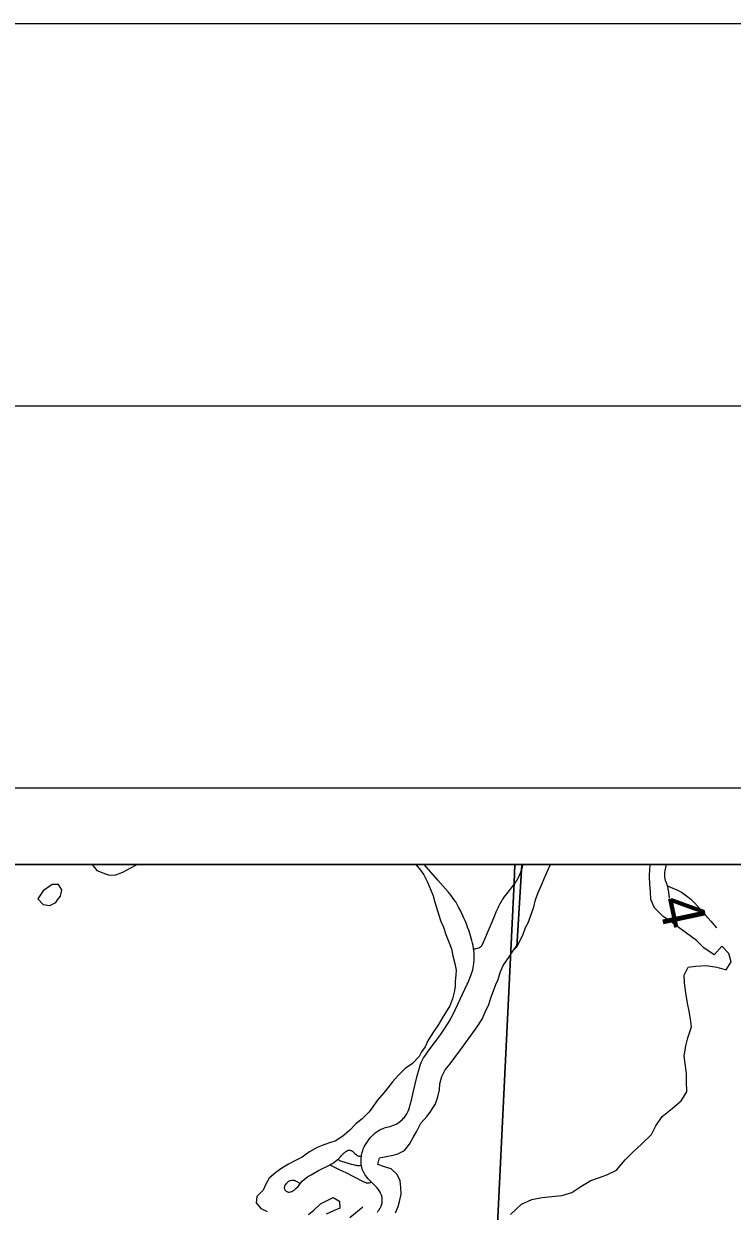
# Model space of a CAD drawing. Extents: x 0 to 34, y -5.4 to 22.
# Drawn here: x 2.87 to 3.798, y 20.446 to 22 of the extents above; entities that cross this region are included whole.
import ezdxf

# ---------------------------------------------------------------- set-up
doc = ezdxf.new("R2010")
doc.units = 0
for name, color, linetype in [('GM_X_County_Road_Text', 7, 'Continuous'), ('GM_X_Major_Lake', 7, 'Continuous'), ('GM_X_Rail_Line', 7, 'Continuous'), ('GM_X_State_Route', 7, 'Continuous'), ('GM_X_Township_Road', 7, 'Continuous'), ('SH_Border', 7, 'Continuous'), ('SH_Cut_Line', 7, 'Continuous'), ('SH_Data', 7, 'Continuous')]:
    doc.layers.add(name, color=color, linetype=linetype)

msp = doc.modelspace()

# ---------------------------------------------------------------- linework, layer by layer
at = {"layer": 'GM_X_Major_Lake'}
for p, q in [((3.5157, 20.7921), (3.5222, 20.9)), ((3.5222, 20.9), (3.5157, 20.7921))]:
    msp.add_line(p, q, dxfattribs=at)
for points in [[(2.96, 20.9), (2.966, 20.892), (2.9739, 20.8888), (2.9822, 20.8861), (2.9909, 20.8863), (3.0001, 20.8896), (3.0089, 20.8944), (3.0188, 20.8999), (3.019, 20.9)], [(3.3836, 20.9), (3.3897, 20.8926), (3.3938, 20.8865), (3.3985, 20.8777), (3.4022, 20.8685), (3.4062, 20.8589), (3.4084, 20.8506), (3.416, 20.8265), (3.4196, 20.8177), (3.4229, 20.8082), (3.4262, 20.7994), (3.4302, 20.7895), (3.4319, 20.7803), (3.4344, 20.7704), (3.4362, 20.7617), (3.4361, 20.7556), (3.4352, 20.7465), (3.4351, 20.7404), (3.4339, 20.7329), (3.4314, 20.7242), (3.4279, 20.7151), (3.4244, 20.7091), (3.4193, 20.7008), (3.4131, 20.6903), (3.4065, 20.6809), (3.3999, 20.67), (3.3956, 20.6614), (3.391, 20.6546), (3.3879, 20.6486), (3.379, 20.6396), (3.3694, 20.6329), (3.3606, 20.6239), (3.3532, 20.6153), (3.3467, 20.6075), (3.3417, 20.6011), (3.3328, 20.591), (3.3266, 20.5816), (3.3219, 20.5756), (3.3131, 20.567), (3.305, 20.5603), (3.2973, 20.5521), (3.2881, 20.5442), (3.2778, 20.5379), (3.2717, 20.5361), (3.2643, 20.5333)], [(3.3571, 20.4441), (3.3606, 20.4524), (3.3622, 20.4588), (3.3643, 20.4686), (3.364, 20.477), (3.363, 20.4857), (3.3593, 20.4942), (3.3511, 20.5015), (3.3425, 20.5043), (3.3338, 20.5075), (3.3358, 20.5158), (3.3446, 20.5179), (3.354, 20.5193), (3.3601, 20.5211), (3.3685, 20.5255), (3.3751, 20.5338), (3.3802, 20.5424), (3.3848, 20.5507), (3.3903, 20.5612), (3.3984, 20.5706), (3.4031, 20.577), (3.4093, 20.5867), (3.4124, 20.5958), (3.4145, 20.6049), (3.415, 20.6128), (3.4174, 20.6223), (3.4221, 20.6313), (3.4283, 20.6392), (3.4348, 20.6475), (3.4422, 20.6572), (3.4561, 20.6767), (3.4639, 20.6876), (3.4705, 20.6974), (3.474, 20.7057), (3.4791, 20.7166), (3.4819, 20.7253), (3.485, 20.7347), (3.4882, 20.743), (3.4913, 20.7494), (3.4941, 20.7585), (3.498, 20.7675), (3.505, 20.7777), (3.5112, 20.7878), (3.5182, 20.7968), (3.5237, 20.8074), (3.5272, 20.8172), (3.5304, 20.8236), (3.5343, 20.8345), (3.5379, 20.8444), (3.5403, 20.8534), (3.5438, 20.8632), (3.5482, 20.8727), (3.5521, 20.8825), (3.5568, 20.8934), (3.5598, 20.9)], [(3.5157, 20.7921), (3.5237, 20.8074), (3.5272, 20.8172), (3.5304, 20.8236), (3.5343, 20.8345), (3.5379, 20.8444), (3.5403, 20.8534), (3.5438, 20.8632), (3.5482, 20.8727), (3.5521, 20.8825), (3.5568, 20.8934), (3.5598, 20.9)], [(3.7176, 20.8248), (3.7078, 20.8314), (3.6959, 20.843), (3.6911, 20.8541), (3.6905, 20.8644), (3.6899, 20.8739), (3.6893, 20.8841), (3.6898, 20.8947), (3.6907, 20.9)], [(2.9147, 20.8535), (2.9185, 20.8586), (2.9201, 20.8665), (2.9157, 20.8738), (2.9077, 20.8736), (2.8959, 20.8656)], [(2.8959, 20.8656), (2.8889, 20.8549), (2.896, 20.8476), (2.9047, 20.8463), (2.9123, 20.8503), (2.9147, 20.8535)], [(3.5075, 20.4417), (3.5217, 20.4552), (3.5354, 20.4614), (3.5491, 20.4639), (3.5616, 20.4652), (3.5746, 20.4669), (3.5875, 20.4705), (3.5994, 20.4786), (3.6127, 20.4864), (3.6238, 20.4904), (3.6337, 20.4937), (3.6463, 20.4999), (3.6575, 20.5134), (3.6679, 20.5239), (3.679, 20.5339), (3.6921, 20.5466), (3.6976, 20.5579), (3.7061, 20.5703), (3.7192, 20.5804), (3.7307, 20.5908), (3.7381, 20.6025), (3.7379, 20.6158), (3.7377, 20.626), (3.7363, 20.6363), (3.7346, 20.6492), (3.7367, 20.6625), (3.7395, 20.6731), (3.7443, 20.6874), (3.7429, 20.6977), (3.7412, 20.7079), (3.7391, 20.7182), (3.737, 20.7319), (3.7353, 20.7449), (3.7347, 20.7551), (3.7398, 20.7653), (3.7497, 20.7666), (3.7637, 20.7676), (3.7777, 20.7655), (3.7898, 20.7618), (3.7964, 20.7727), (3.7931, 20.7834), (3.7842, 20.7931), (3.7738, 20.7818), (3.7606, 20.7908), (3.7509, 20.8004), (3.7378, 20.8101), (3.7281, 20.8171), (3.7176, 20.8248)], [(3.3571, 20.4441), (3.3606, 20.4524), (3.3622, 20.4588), (3.3643, 20.4686), (3.364, 20.477), (3.363, 20.4857), (3.3593, 20.4942), (3.3511, 20.5015), (3.3425, 20.5043), (3.3338, 20.5075), (3.3358, 20.5158), (3.3446, 20.5179), (3.354, 20.5193), (3.3601, 20.5211), (3.3685, 20.5255), (3.3751, 20.5338), (3.3802, 20.5424), (3.3848, 20.5507), (3.3903, 20.5612), (3.3984, 20.5706), (3.4031, 20.577), (3.4093, 20.5867), (3.4124, 20.5958), (3.4145, 20.6049), (3.415, 20.6128), (3.4174, 20.6223), (3.4221, 20.6313), (3.4283, 20.6392), (3.4348, 20.6475), (3.4422, 20.6572), (3.4561, 20.6767), (3.4639, 20.6876), (3.4705, 20.6974), (3.474, 20.7057), (3.4791, 20.7166), (3.4819, 20.7253), (3.485, 20.7347), (3.4882, 20.743), (3.4913, 20.7494), (3.4941, 20.7585), (3.498, 20.7675), (3.505, 20.7777), (3.5112, 20.7878), (3.5157, 20.7921)], [(3.2643, 20.5333), (3.261, 20.5321), (3.2545, 20.5296), (3.2446, 20.524), (3.235, 20.517), (3.2262, 20.5126), (3.2171, 20.5078), (3.2083, 20.5026), (3.2002, 20.4966), (3.1918, 20.4892), (3.1871, 20.4817), (3.1836, 20.4737), (3.1755, 20.4655), (3.1746, 20.4572), (3.1806, 20.4495), (3.1888, 20.446)], [(3.243, 20.4417), (3.2499, 20.4477), (3.2587, 20.4559), (3.2667, 20.4599), (3.2755, 20.4643), (3.2838, 20.4593), (3.284, 20.4502), (3.2756, 20.4465), (3.2661, 20.4421)]]:
    msp.add_lwpolyline(points, dxfattribs=at)
at = {"layer": 'GM_X_Rail_Line'}
for points in [[(3.5133, 20.9), (2.1, 20.9), (2.1, 20.2033), (2.1537, 20.2026), (3.2417, 20.1756), (3.4778, 20.1697), (3.5122, 20.8763)], [(8.9, 19.2127), (8.9, 20.9), (3.5133, 20.9), (3.5122, 20.8763), (3.4778, 20.1697), (3.46, 19.8188), (3.4303, 19.2337), (3.4301, 19.2311), (3.4297, 19.2264), (3.3865, 18.7781), (3.3669, 18.5872), (3.5131, 18.6037), (4.7505, 18.7432), (5.0255, 18.7742), (5.096, 18.7806), (5.378, 18.814), (5.7313, 18.8595), (5.7334, 18.8597), (6.0045, 18.8908), (6.4496, 18.9373), (6.6792, 18.9603), (6.9054, 18.9823), (7.2315, 19.0156), (8.5201, 19.1691)]]:
    msp.add_lwpolyline(points, close=True, dxfattribs=at)
at = {"layer": 'GM_X_State_Route'}
msp.add_lwpolyline([(3.3332, 20.4451), (3.3344, 20.4465), (3.3356, 20.4481), (3.3363, 20.4492), (3.3374, 20.4512), (3.3381, 20.4526), (3.3387, 20.4539), (3.3391, 20.4554), (3.3394, 20.4567), (3.3395, 20.458), (3.3396, 20.4588), (3.3396, 20.4595), (3.3396, 20.4602), (3.3396, 20.4609), (3.3396, 20.4618), (3.3395, 20.4626), (3.3393, 20.4641), (3.339, 20.4655), (3.3389, 20.466), (3.3385, 20.4672), (3.3383, 20.4679), (3.3375, 20.4697), (3.3368, 20.4711), (3.3355, 20.4733), (3.334, 20.4754), (3.333, 20.4767), (3.3312, 20.4787), (3.3292, 20.4806), (3.3267, 20.483), (3.3256, 20.484), (3.3246, 20.485), (3.3223, 20.4873), (3.3211, 20.4886), (3.3194, 20.4907), (3.3181, 20.4923), (3.3167, 20.4944), (3.3153, 20.4968), (3.3145, 20.4985), (3.3135, 20.5011), (3.3127, 20.5035), (3.3123, 20.5054), (3.3122, 20.5063), (3.312, 20.5074), (3.3118, 20.5103), (3.3119, 20.5129), (3.3121, 20.5162), (3.3123, 20.5178), (3.3123, 20.5184), (3.3126, 20.5202), (3.3128, 20.5213), (3.3133, 20.5231), (3.3136, 20.5242), (3.3141, 20.5256), (3.3147, 20.5272), (3.3152, 20.5285), (3.3161, 20.5304), (3.3173, 20.5326), (3.3188, 20.5351), (3.3225, 20.5403), (3.3248, 20.5432), (3.3268, 20.5454), (3.3276, 20.5462), (3.3294, 20.5478), (3.3316, 20.5494), (3.3328, 20.5503), (3.3343, 20.5513), (3.3366, 20.5527), (3.338, 20.5534), (3.3394, 20.554), (3.341, 20.5546), (3.3427, 20.5552), (3.3457, 20.556), (3.3478, 20.5565), (3.3499, 20.5571), (3.3529, 20.5582), (3.3545, 20.5588), (3.3577, 20.5602), (3.3613, 20.5623), (3.3641, 20.5644), (3.3658, 20.5659), (3.3676, 20.5677), (3.3686, 20.5688), (3.3701, 20.571), (3.3717, 20.5737), (3.3733, 20.5772), (3.3742, 20.5792), (3.3748, 20.5807), (3.3756, 20.5835), (3.3761, 20.5854), (3.3781, 20.5931), (3.3801, 20.6013), (3.3827, 20.6125), (3.3854, 20.6234), (3.387, 20.6295), (3.3882, 20.6339), (3.3897, 20.6387), (3.3905, 20.6407), (3.3913, 20.6427), (3.3922, 20.6444), (3.3937, 20.6469), (3.3952, 20.649), (3.3988, 20.6542), (3.4012, 20.6575), (3.4105, 20.6698), (3.4157, 20.677), (3.4211, 20.6848), (3.4234, 20.6884), (3.4257, 20.6921), (3.427, 20.6943), (3.4296, 20.6991), (3.4322, 20.7042), (3.4509, 20.7431), (3.4519, 20.7454), (3.4543, 20.7513), (3.456, 20.7557), (3.458, 20.7619), (3.4587, 20.765), (3.4594, 20.7702), (3.4598, 20.7747), (3.4599, 20.7783), (3.4599, 20.7817), (3.4597, 20.7849), (3.4592, 20.7895), (3.4585, 20.7937), (3.4578, 20.7969), (3.4569, 20.8002), (3.456, 20.8033), (3.4532, 20.8125), (3.4513, 20.8178), (3.4501, 20.821), (3.4484, 20.8253), (3.4469, 20.8289), (3.4423, 20.8389), (3.4396, 20.8442), (3.4373, 20.8484), (3.4357, 20.8509), (3.4334, 20.8541), (3.4297, 20.8591), (3.4257, 20.8642), (3.4124, 20.8795), (3.3946, 20.9)], dxfattribs=at)
at = {"layer": 'GM_X_Township_Road'}
for points in [[(3.4592, 20.7895), (3.4602, 20.7896), (3.4611, 20.7897), (3.4627, 20.79), (3.4641, 20.7903), (3.4658, 20.7909), (3.4673, 20.7916), (3.4682, 20.7921), (3.4688, 20.7927), (3.4694, 20.7932), (3.4698, 20.7937), (3.4704, 20.7947), (3.4711, 20.7959), (3.4721, 20.798), (3.4735, 20.8013), (3.487, 20.8331), (3.4889, 20.8379), (3.4904, 20.8414), (3.4916, 20.8439), (3.4923, 20.8455), (3.494, 20.8487), (3.4951, 20.8507), (3.4961, 20.8525), (3.4967, 20.8534), (3.4977, 20.855), (3.4991, 20.857), (3.5009, 20.8593), (3.5061, 20.8658), (3.5115, 20.8728), (3.5134, 20.8753), (3.5146, 20.8771), (3.5158, 20.8788), (3.5163, 20.8797), (3.5174, 20.8818), (3.5183, 20.8836), (3.5194, 20.8861), (3.5209, 20.8897), (3.522, 20.8928), (3.523, 20.8961), (3.5236, 20.8987), (3.5239, 20.9)], [(3.7156, 20.856), (3.7146, 20.8637), (3.714, 20.8674), (3.7137, 20.8689), (3.7127, 20.8718), (3.7119, 20.8744), (3.7104, 20.8791), (3.71, 20.8813), (3.7096, 20.8834), (3.7095, 20.885), (3.7095, 20.8871), (3.7096, 20.8895), (3.7099, 20.892), (3.7118, 20.9)], [(3.7127, 20.8718), (3.7201, 20.8687), (3.7252, 20.8666), (3.7313, 20.8635), (3.738, 20.8589), (3.7433, 20.8546), (3.7487, 20.8494), (3.7698, 20.8256), (3.777, 20.8171)], [(3.232, 20.4825), (3.2274, 20.485), (3.2266, 20.4854), (3.2262, 20.4857), (3.2257, 20.4858), (3.2252, 20.486), (3.2247, 20.4862), (3.2236, 20.4863), (3.2225, 20.4864), (3.2213, 20.4863), (3.2197, 20.4861), (3.2188, 20.4858), (3.2176, 20.4853), (3.2169, 20.4849), (3.2162, 20.4845), (3.2155, 20.4839), (3.2146, 20.483), (3.2139, 20.4823), (3.213, 20.4812), (3.2123, 20.4801), (3.212, 20.4795), (3.2117, 20.4788), (3.2115, 20.478), (3.2114, 20.4774), (3.2114, 20.4766), (3.2115, 20.4757), (3.2116, 20.4751), (3.212, 20.4742), (3.2128, 20.4733), (3.2137, 20.4725), (3.2147, 20.472), (3.2157, 20.4715), (3.2167, 20.4713), (3.2181, 20.4713), (3.2196, 20.4715), (3.2211, 20.472), (3.2224, 20.4728), (3.2241, 20.4738), (3.2256, 20.4749), (3.2266, 20.4758), (3.2294, 20.4787), (3.2314, 20.4812), (3.2332, 20.4833), (3.2349, 20.4853), (3.2377, 20.4879), (3.2394, 20.4893), (3.2423, 20.4914), (3.2464, 20.4939), (3.2563, 20.4995), (3.2714, 20.5069), (3.2716, 20.5071), (3.2746, 20.5088), (3.2766, 20.5102), (3.2817, 20.5143), (3.2848, 20.5174), (3.2864, 20.519), (3.2881, 20.5208), (3.2899, 20.5226), (3.2906, 20.5232), (3.2913, 20.5239), (3.292, 20.5244), (3.2927, 20.5248), (3.294, 20.5256), (3.295, 20.5259), (3.2959, 20.526), (3.2964, 20.5261), (3.2972, 20.526), (3.2985, 20.5258), (3.2993, 20.5255), (3.2999, 20.5252), (3.3004, 20.5249), (3.301, 20.5244), (3.3018, 20.5236), (3.3039, 20.5215), (3.3055, 20.5202), (3.3064, 20.5195), (3.3069, 20.5192), (3.3074, 20.5189), (3.3078, 20.5188), (3.3085, 20.5185), (3.3094, 20.5183), (3.3106, 20.5181), (3.3123, 20.5178)], [(3.2817, 20.5143), (3.2826, 20.5134), (3.2836, 20.5127), (3.2849, 20.5121), (3.2987, 20.5078), (3.3014, 20.5071), (3.3046, 20.5064), (3.306, 20.5062), (3.3068, 20.5061), (3.3072, 20.506), (3.3097, 20.5061), (3.3122, 20.5063)], [(3.2716, 20.5071), (3.2729, 20.5061), (3.2735, 20.5056), (3.2744, 20.5051), (3.2753, 20.5045), (3.2769, 20.5037), (3.2851, 20.5), (3.288, 20.4987), (3.2918, 20.4969), (3.3139, 20.4853), (3.3153, 20.4847), (3.3168, 20.4841), (3.3184, 20.4835), (3.3201, 20.4832), (3.3215, 20.4831), (3.3224, 20.4832), (3.3243, 20.4837), (3.3256, 20.484)], [(3.2971, 20.4379), (3.3142, 20.4517)]]:
    msp.add_lwpolyline(points, dxfattribs=at)
at = {"layer": 'SH_Border'}
msp.add_lwpolyline([(1.5, 21.5), (33.5, 21.5), (33.5, 0.5), (1.5, 0.5)], close=True, dxfattribs=at)
at = {"layer": 'SH_Cut_Line'}
msp.add_lwpolyline([(0, 0), (34, 0), (34, 22), (0, 22)], close=True, dxfattribs=at)
at = {"layer": 'SH_Data'}
for p, q in [((2, 21), (9, 21)), ((2.1, 20.9), (8.9, 20.9))]:
    msp.add_line(p, q, dxfattribs=at)

# ---------------------------------------------------------------- texts
at = {"layer": 'GM_X_County_Road_Text'}
msp.add_text('4', height=0.0568, rotation=281.9467, dxfattribs=at).set_placement((3.7007, 20.8536))

doc.saveas('drawing.dxf')
